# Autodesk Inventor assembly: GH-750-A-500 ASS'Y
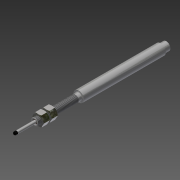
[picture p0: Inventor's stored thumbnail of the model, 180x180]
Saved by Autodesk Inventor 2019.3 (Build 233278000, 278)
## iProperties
Created: 2018-10
Part Number: GH-750-A-500 ASS'Y
Document SubType Name: Weldment
Designer: Justin
Weld Material: Stainless Steel
Mass: 62.4973 g
Surface Area: 311.335 cm^2
Volume: 29.5592 cm^3
Density: 2.11431 g/cm^3
Author: Justin
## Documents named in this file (4)
- C:\Users\Justin\Documents\CAD Drawings\The Sensor Connection\3D\LVDT\GH SERIES\GH-750-A-XXXX\GH-750-A-500\GH-750-A-500 ASS'Y.iam
- C:\Users\Justin\Documents\CAD Drawings\The Sensor Connection\3D\LVDT\GH SERIES\GH-750-A-XXXX\GH-750-A-500\GH-750-A-500 SHAFT_SW.ipt
- C:\Users\Justin\Documents\CAD Drawings\The Sensor Connection\3D\LVDT\GH SERIES\GH-750-A-XXXX\GH-750-A-500\AS 2465 - 1_2  UNF(1).ipt
- C:\Users\Justin\Documents\CAD Drawings\The Sensor Connection\3D\LVDT\GH SERIES\GH-750-A-XXXX\GH-750-A-500\GH-750-A-500 Housing_SW.ipt
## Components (4 placed, 3 different names)
1. GH-750-A-500 SHAFT_SW:1 — Mate:6, Cylindrical:1
2. AS 2465 - Inch 1/2  UNF:1 — Mate:2, Mate:3, Angle:1, Mate:4, Flush:1, Mate:5
3. AS 2465 - Inch 1/2  UNF:2 — Mate:2, Mate:3, Angle:1
4. GH-750-A-500 Housing_SW:1 — Mate:4, Flush:1, Mate:6, Cylindrical:1
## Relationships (8: Mate 5, Angle 1, Flush 1, CylindricalJoint 1)
- Mate:2: AS 2465 - Inch 1/2  UNF:1 ↔ AS 2465 - Inch 1/2  UNF:2
- Mate:3: AS 2465 - Inch 1/2  UNF:1 ↔ AS 2465 - Inch 1/2  UNF:2
- Angle:1: AS 2465 - Inch 1/2  UNF:1 ↔ AS 2465 - Inch 1/2  UNF:2
- Mate:4: AS 2465 - Inch 1/2  UNF:1 ↔ GH-750-A-500 Housing_SW:1
- Flush:1: AS 2465 - Inch 1/2  UNF:1 ↔ GH-750-A-500 Housing_SW:1
- Mate:5: AS 2465 - Inch 1/2  UNF:1
- Mate:6: GH-750-A-500 SHAFT_SW:1 ↔ GH-750-A-500 Housing_SW:1
- Cylindrical:1: GH-750-A-500 SHAFT_SW:1 ↔ GH-750-A-500 Housing_SW:1
